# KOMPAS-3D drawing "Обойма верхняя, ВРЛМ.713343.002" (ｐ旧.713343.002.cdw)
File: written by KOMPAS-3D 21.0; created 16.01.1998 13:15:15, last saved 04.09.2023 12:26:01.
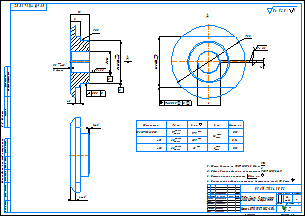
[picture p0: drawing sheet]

Sheet 1: A2, landscape

Document properties: Масса: 0.151638; Знак неуказанной шероховатости: 5; Параметр неуказанной шероховатости: Ra 12,5; v39: 17; v38: 17.9; v37: 1.6; Полное имя файла: D:\2023\Чертежи dwg cdw\ВРЛМ.713343.002.cdw

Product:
- Part/product: Обойма верхняя  | designation ВРЛМ.713343.002
    Материал: Сталь 40Х13 ГОСТ 5632-2014 (density 7650 kg/m3)
    Масса: 0.151638
    additional columns: 17; 17.9; 1.6

Title block, sheet 1: Наименование: Обойма верхняя; designation: ВРЛМ.713343.002; Материал: Сталь 40Х13 ГОСТ 5632-2014; Масса: 0,15; Количество листов документа: 1; Форматы листов документа: A2; stored path: C:\Cadman\Template.sys\template.cdw; Разработал: Бондаренко; Проверил: Соколик; Т. контр.: Соловьева; Н. контр.: Кочерга; Утвердил: Соловьев; Разработал, date: 22.03.2023; cell 140: 3; cell 160: ВРЛМ.022-23; cell 180: 29.03.2023

Views: Вид 4, Местный разрез 1, Спереди, Вид по стрелке 6, Проекционный вид 7, Вид:1, Вид:2
Referenced files in D:\2023\Чертежи dwg cdw\: ВРЛМ.713343.002.m3d
Referenced files in W:\ВРЛМ.713343.002\: ВРЛМ.713343.002.m3d
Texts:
  Обычный
  Термин
  Список определений
  Адрес
  Цитаты
  Форматированный
  Courier New
  Z-конец формы
  Z-начало формы
  Согласовано: нач. отд. метрологии           Н. Н. Палкина
  Ra 3,2
  h, мм
  b, мм
  Масса, кг
  ВРЛМ.713343.002 - 01
  ВРЛМ.713343.002-01
  ВРЛМ.713343.002 - 02
  ВРЛМ.713343.002-02
  Стиль таблицы исполнений
  @2~d, мм
  h, мм@151~
  Ra 6,3
  Ra 12,5
  Ra 12,5 ( )
  SLDSECTION2_RGB_0_0_0_SC_1.000000.2
  Стили документа
  ВРЛМ.304421.006.000
  Зам.
  ВРЛМ.713343.002 Обойма верхняя
Dimensions and other numbers on the sheet: 4,5; 8; 15; 0,3; 2 фаски; 33; 0,05; 0,5; 17 +0,075 +0,032; 17,9 +0,2; 1,6 +0,12 +0,02; 0,15; -01; 20 +0,092 +0,040; 20,9 +0,2; 0,14; -02; 22 +0,092 +0,040; 23 +0,2; 2 +0,12 +0,02; 0,13; 17$m+0,075;+0,032$; 17,9$m+0,2;$; 1,6$m+0,12;+0,02$; 20$m+0,092;+0,040$; 20,9$m+0,2;$; 22$m+0,092;+0,040$; 23$m+0,2;$; 2$m+0,12;+0,02$; 39,5; 58; 1; 4; 22.03.2023; 3; 29.03.2023

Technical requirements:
  Общие допуски по ГОСТ 30893.1: h14,  IT14 2 .
  Общие допуски формы и расположения ГОСТ 30893.2-К.
  Острые кромки притупить  0,3 -0,2 мм.
  Неуказанные радиусы скругления внутренних углов R0,5 max.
